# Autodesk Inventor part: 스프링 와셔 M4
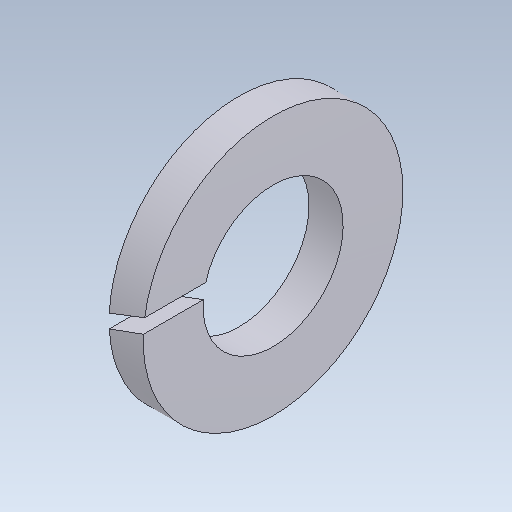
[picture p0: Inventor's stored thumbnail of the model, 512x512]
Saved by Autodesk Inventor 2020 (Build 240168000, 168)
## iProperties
Created: 2024-04
Part Number: 스프링 와셔 M4
Material: 강철, 연강
Description: 스프링 와셔
Document SubType Name: Modeling
Designer: oem
Density: 7.85 g/cm^3
Appearance: 기본값
Mass: 0.246957 g
Surface Area: 1.02615 cm^2
Volume: 0.0314594 cm^3
Sending System: Autodesk Inventor 2025
Preprocessor: ST-DEVELOPER v20
Author: jhkim
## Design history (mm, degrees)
feature "Solid1"
node "솔리드1"
